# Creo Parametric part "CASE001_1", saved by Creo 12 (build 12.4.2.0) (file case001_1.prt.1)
Units: Custom; MM, KILOGRAM, SECS

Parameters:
  PTC_WM_ITERATION = "0"
  PTC_WM_VERSION = "-.0"
  PTC_WM_LIFECYCLE_STATE = "In Work"
  PTC_WM_LIFECYCLE = "MO_CADDocument"
  PTC_WM_CREATED_BY = "Maximilian Roepper (Z0017RMS: MO)"
  PTC_WM_CREATED_ON = "18-Sep-26 11:36:42 AM"
  PTC_WM_MODIFIED_BY = "Maximilian Roepper (Z0017RMS: MO)"
  PTC_WM_MODIFIED_ON = "18-Sep-26 11:36:46 AM"
  PDMLINKNUMBER = "PDM000071454913"
  PTC_WM_NAME = "case001_1.prt"
  PTC_WM_NUMBER = "PDM000071454913"

Other parameters: WEIGHT, WEIGHT_FACTOR, WEIGHT_ADD, _MASS_TEMP, _DIFF_TEMP, MC_ERRORS, SUPPLIER

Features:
  1. coordinate system
  2. datum plane "PRT_YZ"
  3. datum plane "PRT_XY"
  4. datum plane "PRT_XZ"
  5. coordinate system
  6. datum axis
  7. datum axis
  8. datum axis
  9. coordinate system
  10. imported feature
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
Other named items: PRT, SIEMENS_MO, DRW_VIEW_ORG, PRT_X, PRT_Y, PRT_Z, CS0, ROUGH_GROB

Layers: 00_STD_CSYS-KSYS, 01_STD_PLANES-EBENEN, 02_STD_AXES-ACHSEN, 03_STD_CSYS-KSYS, 24_IMPORT_FEAT-IMPORT_KE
